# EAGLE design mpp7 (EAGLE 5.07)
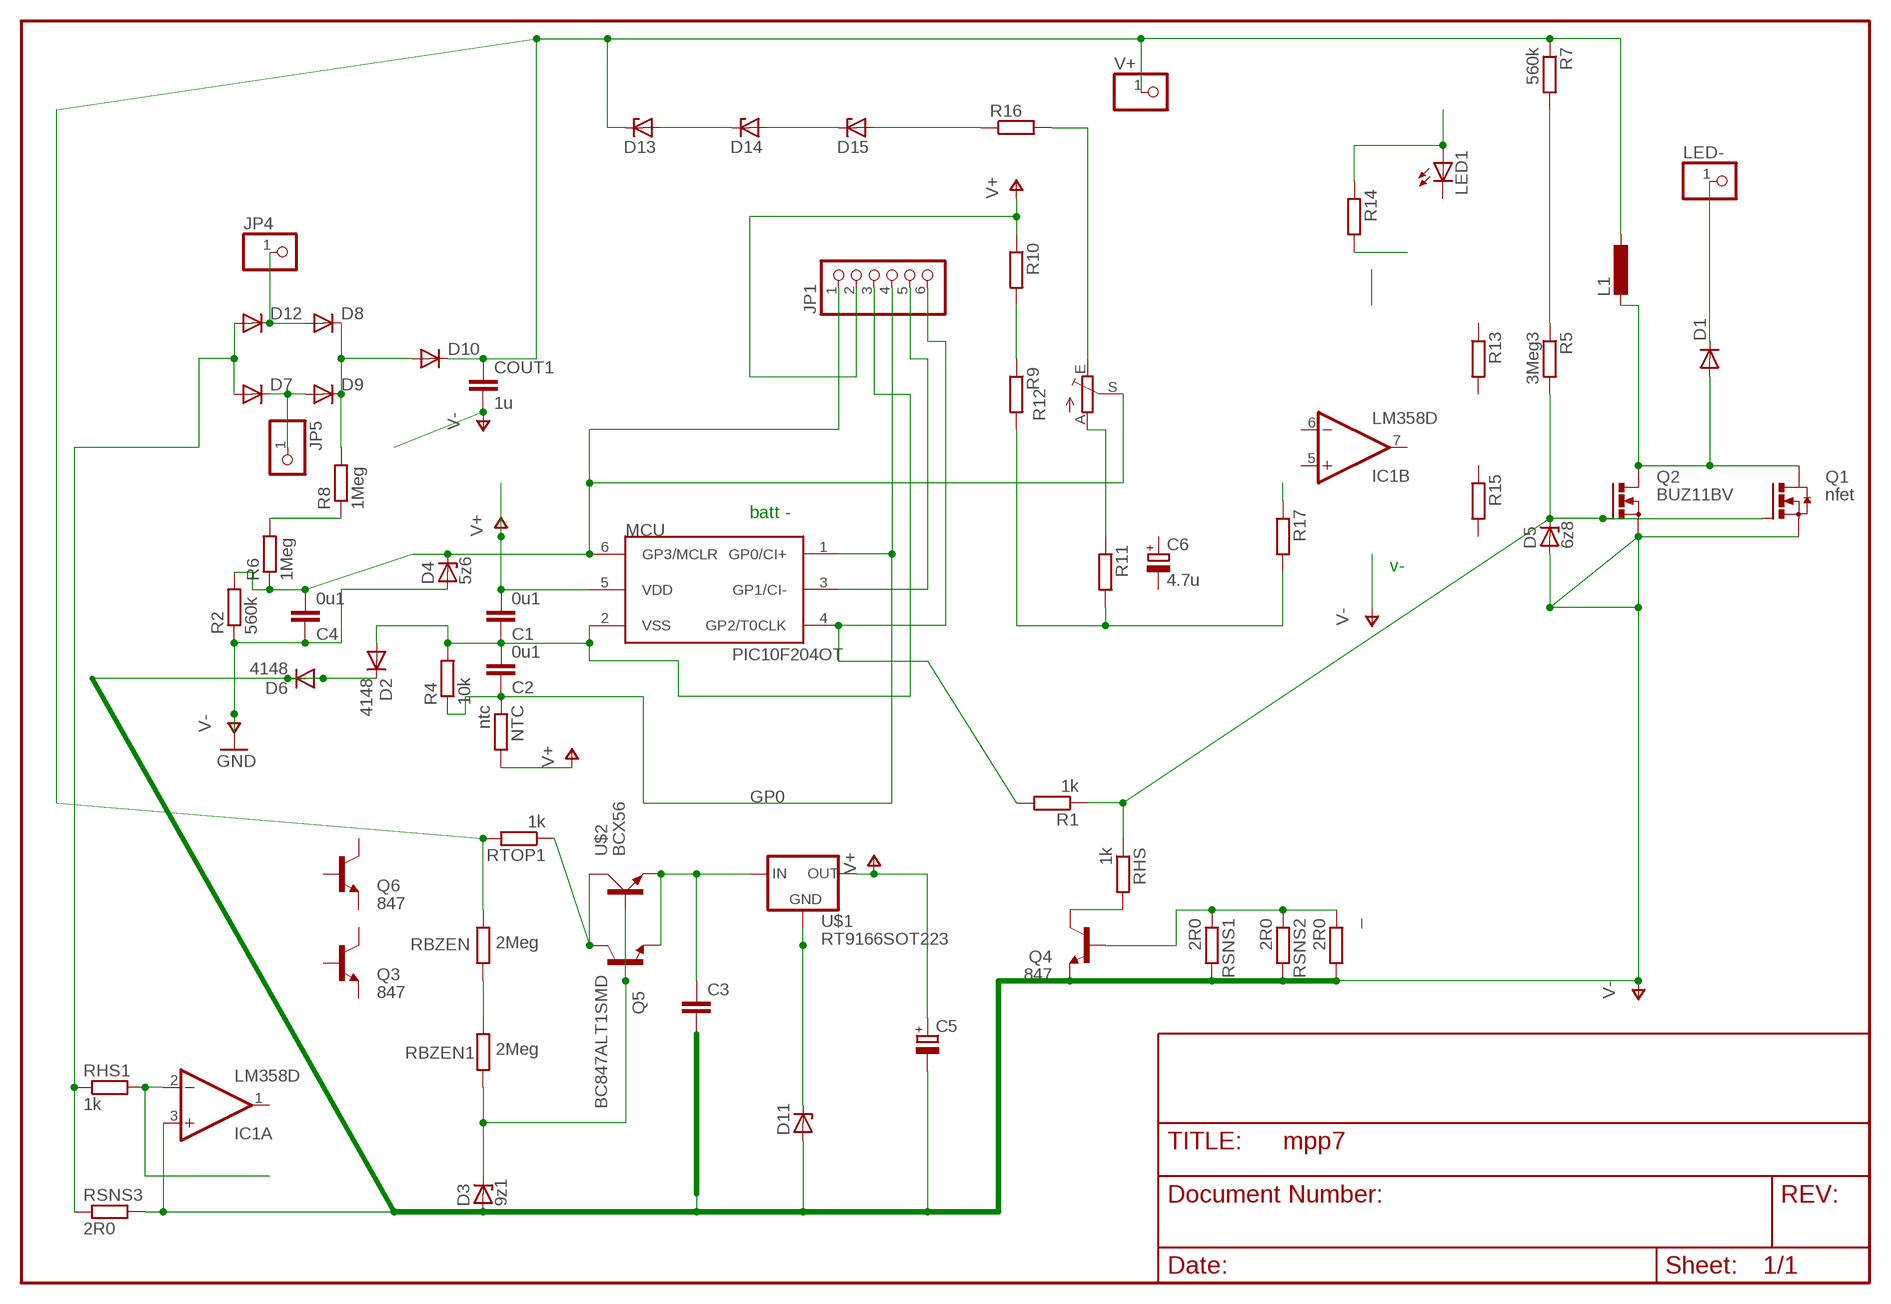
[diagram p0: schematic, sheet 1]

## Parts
_  2R0  R-EU_R2010  [R2010]
C1  0u1  C-EUC0805  [C0805]
C2  0u1  C-EUC0805  [C0805]
C3  C-EUC1206  [C1206]
C4  0u1  C-EUC1206  [C1206]
C5  CPOL-EUSANYO_SMD_B6  [SANYO-OSCON_SMD_B6]
C6  4.7u  CPOL-EUSANYO_SMD_C6  [SANYO-OSCON_SMD_C6]
COUT1  1u  C-EU075-032X103  [C075-032X103]
D1  DIODE-SMC  [SMC]
D2  4148  1N4148MINIMELF  [MINIMELF]
D3  9z1  ZENER-DIODESOD80C  [SOD80C]
D4  5z6  ZENER-DIODESOD80C  [SOD80C]
D5  6z8  ZENER-DIODESOD80C  [SOD80C]
D6  4148  1N4148MINIMELF  [MINIMELF]
D7  DIODE-SMA-DO214  [SMA-DO214AC]
D8  DIODE-SMA-DO214  [SMA-DO214AC]
D9  DIODE-SMA-DO214  [SMA-DO214AC]
D10  DIODE-SMA-DO214  [SMA-DO214AC]
D11  ZENER-DIODESOD80C  [SOD80C]
D12  DIODE-SMA-DO214  [SMA-DO214AC]
D13  ZENER-DIODESOD80C  [SOD80C]
D14  ZENER-DIODESOD80C  [SOD80C]
D15  ZENER-DIODESOD80C  [SOD80C]
IC1  LM358D  [SO08]
JP1  PINHD-1X6  [1X06BOX]
JP4  PINHD-1X11MM6  [1X1MM8]
JP5  PINHD-1X11MM6  [1X1MM8]
L1  L-EUPIS2816  [PIS2816]
LED1  LEDCHIPLED_1206  [CHIPLED_1206]
LED-  PINHD-1X11MM6  [1X1MM8]
MCU  PIC10F204OT  [SOT23-6]
NTC  ntc  R-EU_0204/5  [0204/5]
Q1  nfet  N-HEXFET_DPAK-  [TO252]
Q2  BUZ11BV  [TO220BV]
Q3  847  BC847ASMD  [SOT23]
Q4  847  BC847ASMD  [SOT23]
Q5  BC847ALT1SMD  [SOT23]
Q6  847  BC847ASMD  [SOT23]
R1  1k  R-EU_R0805  [R0805]
R2  560k  R-EU_R0805  [R0805]
R4  10k  R-EU_R0805  [R0805]
R5  3Meg3  R-EU_R1206  [R1206]
R6  1Meg  R-EU_R1206  [R1206]
R7  560k  R-EU_R1206  [R1206]
R8  1Meg  R-EU_R1206  [R1206]
R9  R-EU_R0805  [R0805]
R10  R-EU_R0805  [R0805]
R11  R-EU_R1206  [R1206]
R12  TRIM_EU-S64W  [S64W]
R13  R-EU_R1206  [R1206]
R14  R-EU_R0805  [R0805]
R15  R-EU_R0805  [R0805]
R16  R-EU_R0805  [R0805]
R17  R-EU_R0805  [R0805]
RBZEN  2Meg  R-EU_R1206  [R1206]
RBZEN1  2Meg  R-EU_R1206  [R1206]
RHS  1k  R-EU_0204/5  [0204/5]
RHS1  1k  R-EU_0204/5  [0204/5]
RSNS1  2R0  R-EU_R2512  [R2512]
RSNS2  2R0  R-EU_R1206  [R1206]
RSNS3  2R0  R-EU_R2512  [R2512]
RTOP1  1k  R-EU_R1206  [R1206]
U$1  RT9166SOT223  [SOT223]
U$2  BCX56  [SOT223]
V+  PINHD-1X11MM6  [1X1MM8]

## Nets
A: R11.1 R12.A
AC1: D8.A D12.K(C) JP4.1
AC2: D7.K(C) D9.A JP5.1
BSW1: _.1 Q4.1(B) RSNS1.1 RSNS2.1
C: Q5.3(C) RTOP1.1 U$2.2(C)
CB: D3.C Q5.1(B) RBZEN1.2 U$2.1(B)
GND1: D11.C U$1.2(GND) U$1.4(GND1)
GP0: C2.1 JP1.4 MCU.1(GP0/CI+) NTC.1 R4.1
HOT: D1.A L1.2 Q1.3(D) Q2.D
LED-: D1.C LED-.1
N$1: D5.C Q1.1(G) Q2.G R1.1 R5.2 RHS.1
N$2: C3.1 Q5.2(E) U$1.3(IN) U$2.3(E)
N$3: C4.2 D4.C JP1.1 MCU.6(GP3/MCLR) R2.2 R6.1 R12.S
N$4: R5.1 R7.2
N$5: IC1.2(A:-IN) RHS1.2
N$6: RBZEN1.1 RBZEN.2
N$7: Q4.3(C) RHS.2
N$8: R9.1 R10.2
N$9: R6.2 R8.1
N$10: JP1.5 MCU.3(GP1/CI-)
N$12: LED1.A R14.1
N$14: JP1.6 MCU.4(GP2/T0CLK) R1.2
N$15: D7.A D12.A RHS1.1 RSNS3.1
N$16: D8.K(C) D9.K(C) D10.A R8.2
N$17: R14.2
N$18: D15.A R16.1
N$20: D14.A D15.C
N$21: D13.A D14.C
N$23: R12.E R16.2
N$24: R17.1
V+: C1.2 C5.+ JP1.2 MCU.5(VDD) NTC.2 R10.1 U$1.1(OUT)
V-: _.2 C3.2 C4.1 C5.- COUT1.2 D2.C D3.A D4.A D5.A D6.A D6.C D11.A IC1.3(A:+IN) Q1.2(S) Q2.S Q4.2(E) R2.1 R9.2 R11.2 R17.2 RSNS1.2 RSNS2.2 RSNS3.2 ; supply symbol labelled GND
VPLUS: COUT1.1 D10.K(C) D13.C L1.1 R7.1 RBZEN.1 RTOP1.2 V+.1
VSS: C1.1 C2.2 D2.A JP1.3 MCU.2(VSS) R4.2
Unconnected: C6.+ C6.- IC1.1(A:OUT) IC1.5(B:+IN) IC1.6(B:-IN) IC1.7(B:OUT) LED1.C Q3.1(B) Q3.2(E) Q3.3(C) Q6.1(B) Q6.2(E) Q6.3(C) R13.1 R13.2 R15.1 R15.2

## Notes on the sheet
- batt -
- v-

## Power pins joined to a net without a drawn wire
V+: IC1.8(P:V+)
V-: IC1.4(P:V-)

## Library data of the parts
_ NTC R1 R5 R7 R9-R11 R13-R17 RBZEN RBZEN1 RHS RHS1 RSNS1-RSNS3 RTOP1 = rcl:R-EU_: RESISTOR, European symbol
C1-C4 COUT1 = rcl:C-EU: CAPACITOR, European symbol
C5 = rcl-2:CPOL-EU: POLARIZED CAPACITOR, European symbol
C6 = rcl:CPOL-EU: POLARIZED CAPACITOR, European symbol
D1 = diode-1:DIODE-: DIODE
D2 D6 = diode-1:1N4148: DIODE
D3-D5 D11 D13-D15 = diode:ZENER-DIODE: Z-Diode
D7-D10 D12 = diode:DIODE-: DIODE
IC1 = linear:LM358: OP AMP also LM158; LM258; LM2904 Source: http://cache.national.com/ds/LM/LM158.pdf
JP1 = pinhead:PINHD-1X6: PIN HEADER
JP4 JP5 LED- V+ = pinhead:PINHD-1X1: PIN HEADER
L1 = rcl:L-EU: INDUCTOR, European symbol
LED1 = led:LED: LED
MCU = microchip-3:PIC10F2*: uPC nW 0,25/0,5k Program Flash memory Comparator
Q1 = transistor-power:N-HEXFET_?-*: HEXFET® Power MOSFET
Q2 = transistor-power:BUZ11: N-CHANNEL MOS FET
Q3-Q6 = transistor-npn:BC847*: NPN Transistor
R2 R4 R6 R8 = rcl-2:R-EU_: RESISTOR, European symbol
R12 = pot:TRIM_EU-: POTENTIOMETER
U$1 = v-reg:RT9166
U$2 = transistor-power:BCX56

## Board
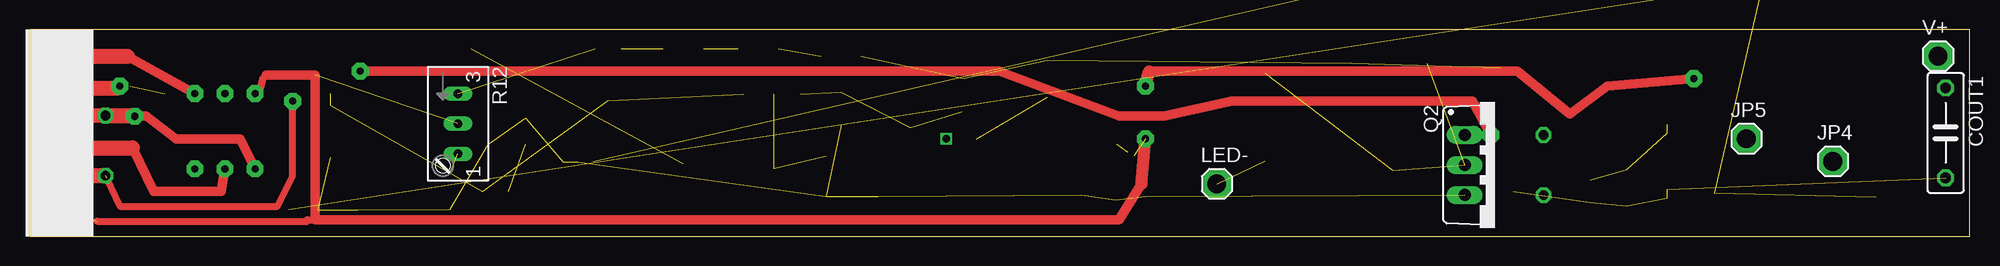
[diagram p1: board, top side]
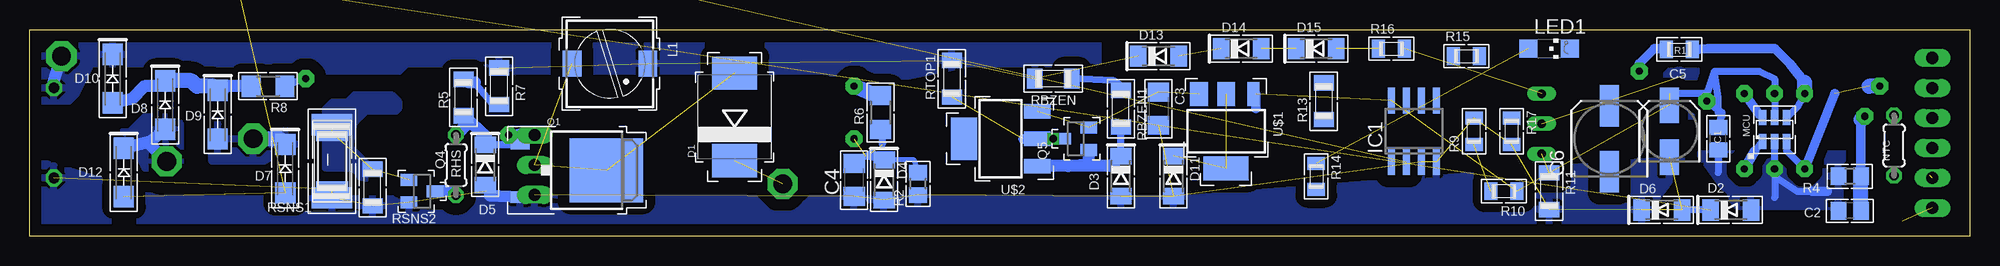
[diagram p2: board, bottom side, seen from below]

Size 163.99 x 17.5 mm. Coordinates in mm from the lower left corner, seen from the top.
Outline: 0,0 163.99,0 163.99,17.5 0,17.5 0,0
Copper layers (1*16): Top 0.035mm / dielectric 1.5mm / Bottom 0.035mm
Design rules "default *": minimum track width 10mil, minimum drill 24mil, track to track 8mil, track to pad 8mil, pad to pad 8mil, via to via 8mil, smd to smd 8mil, copper to edge 20mil, drill to drill 8mil, minimum pad ring 10mil, minimum via ring 8mil, stop-mask expansion 4mil, vias tented up to drill 0mil, thermal gap 10mil

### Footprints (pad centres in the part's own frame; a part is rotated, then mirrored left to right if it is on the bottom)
R2010 = smd 1.4 x 2.7: 1 -2.4,0; 2 2.4,0
C0805 = smd 1.3 x 1.5: 1 -0.95,0; 2 0.95,0
C1206 = smd 1.6 x 1.8: 1 -1.4,0; 2 1.4,0
SANYO-OSCON_SMD_B6 = smd 3 x 1.6: + 2.2,0; - -2.2,0
SANYO-OSCON_SMD_C6 = smd 3.5 x 1.6: + 2.8,0; - -2.8,0
C075-032X103 = drill 0.914 octagon: 1 -3.81,0; 2 3.81,0
SMC = smd 2.8 x 3.8: A 3.7,0; C -3.7,0
MINIMELF = smd 1.4 x 1.8: A 1.7,0; C -1.7,0
SOD80C = smd 1.4 x 1.8: A 1.7,0; C -1.7,0
SMA-DO214AC = smd 1.8 x 1.7: A 2.05,-0.127; K -2.05,-0.127
SO08 = smd 0.6 x 2.2: 1 -1.905,-2.6; 2 -0.635,-2.6; 3 0.635,-2.6; 4 1.905,-2.6; 5 1.905,2.6; 6 0.635,2.6; 7 -0.635,2.6; 8 -1.905,2.6
1X06BOX = drill 1.016 long: 1 -6.35,0; 2 -3.81,0; 3 -1.27,0; 4 1.27,0; 5 3.81,0; 6 6.35,0
1X1MM8 = drill 1.6 pad 2.54 octagon: 1 0,0
PIS2816 = smd 2.2 x 1.6: 1 0,3.2; 2 0,-3.2
CHIPLED_1206 = smd 1.5 x 1.5: A 0,-1.75; C 0,1.75
SOT23-6 = smd 0.635 x 1.27: 1 -1.016,-1.016; 2 0,-1.016; 3 1.016,-1.016; 4 1.016,1.016; 5 0,1.016; 6 -1.016,1.016
0204/5 = drill 0.813 octagon: 1 -2.54,0; 2 2.54,0
TO252 = smd 1 x 1.6: 1 -2.28,-3.53; 2 2.28,-3.53 | smd 5.4 x 6.2: 3 0,3.77
TO220BV = drill 1.016 long: D 0,-2.54; G -2.54,-2.54; S 2.54,-2.54
SOT23 = smd 1 x 1.4: 1 -0.95,-1.1; 2 0.95,-1.1; 3 0,1.1
R0805 = smd 1.1 x 1.5: 1 -1.1,0; 2 1.1,0
R0805' = smd 1.3 x 1.5: 1 -0.95,0; 2 0.95,0
R1206 = smd 1.3 x 1.7: 1 -1.55,0; 2 1.55,0
R1206' = smd 1.6 x 1.803: 1 -1.422,0; 2 1.422,0
S64W = drill 0.7 long: A 2.54,1.27; E -2.54,1.27; S 0,1.27
R2512 = smd 1.8 x 3.4: 1 -3.1,0; 2 3.1,0
SOT223 = smd 1 x 2: 1 -2.3,-3.15 | smd 1.5 x 2: 2 0,-3.15; 3 2.3,-3.15 | smd 3.8 x 2: 4 0,3.15
SOT223' = smd 1.219 x 2.235: 1 -2.311,-3.099; 2 0,-3.099; 3 2.311,-3.099 | smd 3.6 x 2.2: 4 0,3.099

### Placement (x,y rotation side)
_  138.43,6.35 270 bottom
C1  21.27,8.26 90 bottom
C2  10.16,2.16 180 bottom
C3  68.58,10.79 270 bottom
C4  94.3,4.76 90 bottom
C5  25.4,8.89 90 bottom
C6  30.48,8.26 90 bottom
COUT1  161.93,8.75 270 top
D1  104.39,10.1 90 bottom
D2  20.2,2.22 0 bottom
D3  71.75,5.08 270 bottom
D4  91.76,4.76 270 bottom
D5  125.48,6.03 270 bottom
D6  26.04,2.22 0 bottom
D7  142.24,5.71 270 bottom
D8  152.4,11.11 270 bottom
D9  147.96,10.29 270 bottom
D10  156.84,13.34 270 bottom
D11  67.31,5.08 270 bottom
D12  155.89,5.4 270 bottom
D13  68.58,15.24 0 bottom
D14  61.59,15.88 0 bottom
D15  55.24,15.88 0 bottom
IC1  46.99,8.89 0 bottom
JP1  3.17,8.75 90 top
JP4  152.4,6.35 0 top
JP5  145.1,8.26 0 top
L1  114.94,14.61 270 bottom
LED1  35.56,15.88 270 bottom
LED-  100.33,4.45 0 top
MCU  16.51,9.03 0 bottom
NTC  6.41,7.68 270 bottom
Q1  119,5.59 270 bottom
Q2  123.83,6.03 270 top
Q3  not placed on the board
Q4  130.81,3.81 270 bottom
Q5  75.56,8.26 90 bottom
Q6  not placed on the board
R1  24.57,15.81 0 bottom
R2  560k  [R0805']  88.9,4.45 90 bottom
R4  10k  [R0805']  10.16,5.08 180 bottom
R5  127.32,11.75 270 bottom
R6  1Meg  [R1206']  92.08,10.48 90 bottom
R7  124.3,12.7 270 bottom
R8  1Meg  [R1206']  143.83,12.7 180 bottom
R9  41.91,8.89 90 bottom
R10  39.37,3.81 180 bottom
R11  35.56,3.81 270 bottom
R12  34.92,9.53 270 top
R13  54.61,11.43 90 bottom
R14  55.24,5.08 270 bottom
R15  42.55,15.24 0 bottom
R16  48.9,15.88 0 bottom
R17  38.73,8.89 270 bottom
RBZEN  77.47,13.34 0 bottom
RBZEN1  71.75,10.79 270 bottom
RHS  127.95,6.03 270 bottom
RHS1  not placed on the board
RSNS1  138.43,6.35 270 bottom
RSNS2  135,4.13 270 bottom
RSNS3  not placed on the board
RTOP1  86.04,13.34 90 bottom
U$1  62.87,8.89 180 bottom
U$2  BCX56  [SOT223']  81.92,8.26 90 bottom
V+  161.29,15.24 0 top

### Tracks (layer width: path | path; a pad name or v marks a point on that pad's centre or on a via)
A  (1 unrouted)
AC1
  Bottom 1.016: 154,7.95 D12.K | JP4.1 154,7.95 | 154,7.95 153.87,7.95 D8.A
  pour Bottom (isolate 0.813, rank 2): 151.76,10.16 154.31,10.16 155.57,8.89 156.21,8.89 155.57,8.26 154.31,5.71 151.13,5.71 151.13,9.53
AC2
  Bottom 1.27: JP5.1 142.86,8.26 D7.K
  pour Bottom (isolate 0.813): 148.59,9.53 141.6,8.89 141.6,7.62 144.15,6.35 148.59,6.35
BSW1  (3 unrouted)
  pour Bottom (isolate 0.813, rank 2, no thermals): 139.06,5.71 139.06,10.79 138.43,11.43 137.16,11.43 136.53,12.06 133.35,12.06 132.72,11.43 132.72,10.79 133.03,10.48 135.57,10.48 136.53,9.53 136.84,7.62 135.57,6.35 135.57,4.76
C  (via drill 0.6)  (1 unrouted)
  Bottom 0.813: 80.01,8.26 v77.47,8.26 Q5.3
  Bottom 1.016: Q5.3 U$2.2
CB
  Bottom 0.61: D3.C RBZEN1.2 | 78.42,5.94 U$2.1
  Bottom 1.016: 76.2,5.94 72.59,5.94 D3.C | 76.2,5.94 78.42,5.94 | Q5.1 74.47,6.11 76.2,5.94
GND1  (2 unrouted)
GP0  (via drill 0.6 pad 1.42)
  Top 0.61: 3.31,10.16 JP1.4
  Top 0.813: v19.05,5.71 17.78,8.26 12.38,8.26 9.84,10.16 v8.89,10.16 | 5.14,10.16 5.08,10.16 | 6.48,10.16 NTC.1
  Top 1.27: 5.08,10.16 3.31,10.16 | NTC.1 5.14,10.16 | v8.89,10.16 6.48,10.16
  Bottom 0.61: 18.16,7.24 MCU.1
  Bottom 0.813: v19.05,5.71 18.16,7.24 | R4.1 9.21,9.84
  Bottom 1.27: 9.21,9.84 v8.89,10.16 | C2.1 R4.1
HOT  (3 unrouted)
LED-  (1 unrouted)
N$1  (via drill 0.6 pad 1.42)
  Top 0.813: v123.51,8.57 121.92,11.43 101.6,11.43 95.89,10.16 92.08,10.16 81.92,13.97 v27.94,13.97
  Bottom 0.406: D5.C 125.41,8.42 | R5.2 127,9.53
  Bottom 0.61: D5.C 122.79,7.73 Q1.1 122.53,8.87 v123.51,8.57 Q2.G | R1.1 25.59,15.88
  Bottom 0.813: v27.94,13.97 27.94,14.61 26.67,15.88 25.59,15.88
  Bottom 1.016: 125.41,8.42 R5.2 | 127,9.53 RHS.1
N$2  (3 unrouted)
N$3  (via drill 0.6 pad 1.42)  (4 unrouted)
  Top 0.61: 5.71,1.27 23.5,1.27 23.5,1.4 24.13,1.4 | 20,13.65 19.68,13.34 19.37,12.06 v19.05,12.06
  Top 0.813: 20,13.65 24.13,13.65 24.13,1.4 92.08,1.4 93.98,4.45
  Top 1.016: 93.98,4.45 v94.3,8.26
  Bottom 0.406: R2.2 89.22,6.46 D4.C
  Bottom 0.61: 17.78,10.3 MCU.6 | C4.2 93.33,6.8 D4.C 92.82,7.1 | R6.1 91.91,7.79
  Bottom 0.813: v19.05,12.06 17.78,10.3
N$4
  Bottom 0.406: R7.2 124.94,11.28 | 126.85,13.02 R5.1
  Bottom 0.61: 124.94,11.28 126.36,13.02
  Bottom 1.016: 126.36,13.02 126.85,13.02
N$5  (1 unrouted)
N$6
  Bottom 0.61: RBZEN1.1 71.75,12.7 72.39,13.18 RBZEN.2
N$7
  Bottom 0.406: RHS.2 128.42,3.81
  Bottom 1.016: 128.42,3.81 Q4.3
N$8  (1 unrouted)
N$9  (via drill 0.6 pad 1.42)
  Top 0.813: 94.61,13.97 125.73,13.97 130.18,10.34 133.35,12.7 v140.65,13.34
  Top 1.016: v94.3,12.7 94.61,13.97
  Bottom 0.61: R6.2 92.86,12.06 | v140.65,13.34 R8.1
  Bottom 1.27: 92.86,12.06 v94.3,12.7
N$10  (via drill 0.6 pad 1.42)  (1 unrouted)
  Top 0.406: 7.48,12.56 v7.62,12.7
  Top 1.27: JP1.5 7.48,12.56
  Bottom 0.406: 15.49,7.24 MCU.3
  Bottom 0.61: v13.97,5.71 15.49,7.24
  Bottom 0.813: v13.97,5.71 11.43,12.06
  Bottom 1.27: v7.62,12.7 8.51,12.7
N$12  (1 unrouted)
N$14  (via drill 0.6 pad 1.42)
  Top 0.813: 8.26,15.24 v13.97,12.06 | JP1.6 3.31,15.24
  Top 1.27: 3.31,15.24 8.26,15.24
  Bottom 0.61: v13.97,12.06 14.61,10.94 MCU.4
  Bottom 0.813: R1.2 22.16,15.88 16.51,15.88 15.24,14.61 13.97,13.02
  Bottom 1.27: v13.97,12.06 13.97,13.02
N$15  (3 unrouted)
N$16
  Bottom 1.016: D10.A 155.37,11.63 154.31,12.7 152.51,12.7 D8.K | D9.K 147.96,12.06 147.32,12.7 R8.2
  Bottom 1.27: D8.K 150.32,13.16 149.86,12.7 148.44,12.7 D9.K
N$18  (1 unrouted)
N$20  (1 unrouted)
N$21  (1 unrouted)
N$23  (1 unrouted)
V+  (via drill 0.6 pad 1.42)  (6 unrouted)
  Top 0.61: 6.49,4.94 7.62,2.54 20.95,2.54 22.23,5.08 v22.23,11.43
  Top 1.27: 3.38,5.14 NTC.2
  Bottom 0.61: MCU.5 v16.51,12.06 16.51,13.34 17.78,13.97 21.59,13.97 | 25.4,12.06 22.23,12.06 21.59,13.97 | 21.59,13.97 21.27,11.75 21.27,10.48 20.95,10.16 C1.2 20.96,10.48 v22.23,11.43
  Bottom 0.813: U$1.1 60.33,12.04 60.33,10.79
V-  (20 unrouted)
  Bottom 0.61: Q2.S 122.53,3.49 Q1.2 | 125.09,3.42 125.09,3.81 125.41,3.81 D5.A | D2.C D6.A
  Bottom 1.016: Q1.2 125.09,3.42
  pour Bottom (isolate 1.016, rank 4): 66.67,3.17 153.03,3.17 163.19,6.35 163.19,0.64 26.99,0.64 26.99,2.54 24.13,6.35 27.3,6.35
VDD
  pour Bottom (isolate 0.813, rank 2): 24.77,10.16 13.34,10.16 13.34,13.97 13.97,14.61 24.77,14.61 26.04,13.34
VPLUS  (4 unrouted)
  Bottom 1.016: V+.1 161.93,13.2 COUT1.1
  pour Bottom (isolate 1.016, rank 3): 163.51,15.88 163.19,13.65 163.19,11.43 160.66,11.43 160.02,12.06 158.75,14.61 154.31,14.61 153.67,13.97 132.72,13.97 132.08,14.61 125.09,14.61 124.46,13.97 96.52,13.97 94.61,12.7 93.98,12.7 84.45,14.61 73.66,14.61 73.66,16.51 161.93,16.51
VSS  (via drill 0.6 pad 1.42)
  Top 0.813: 8.71,7.48 10.48,3.81 16.19,3.81 v16.51,5.71
  Top 1.27: JP1.3 8.71,7.48
  Bottom 0.61: C1.1 21.27,5.4 | 16.51,5.08 v16.51,5.71 MCU.2 | 16.51,5.08 16.51,3.27 | 16.51,5.08 14.61,3.81 13.34,3.81
  Bottom 0.813: 13.34,3.81 12.06,3.81
  pour Bottom (isolate 0.813): 9.53,6.99 22.86,6.99 19.68,2.54 5.71,2.54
